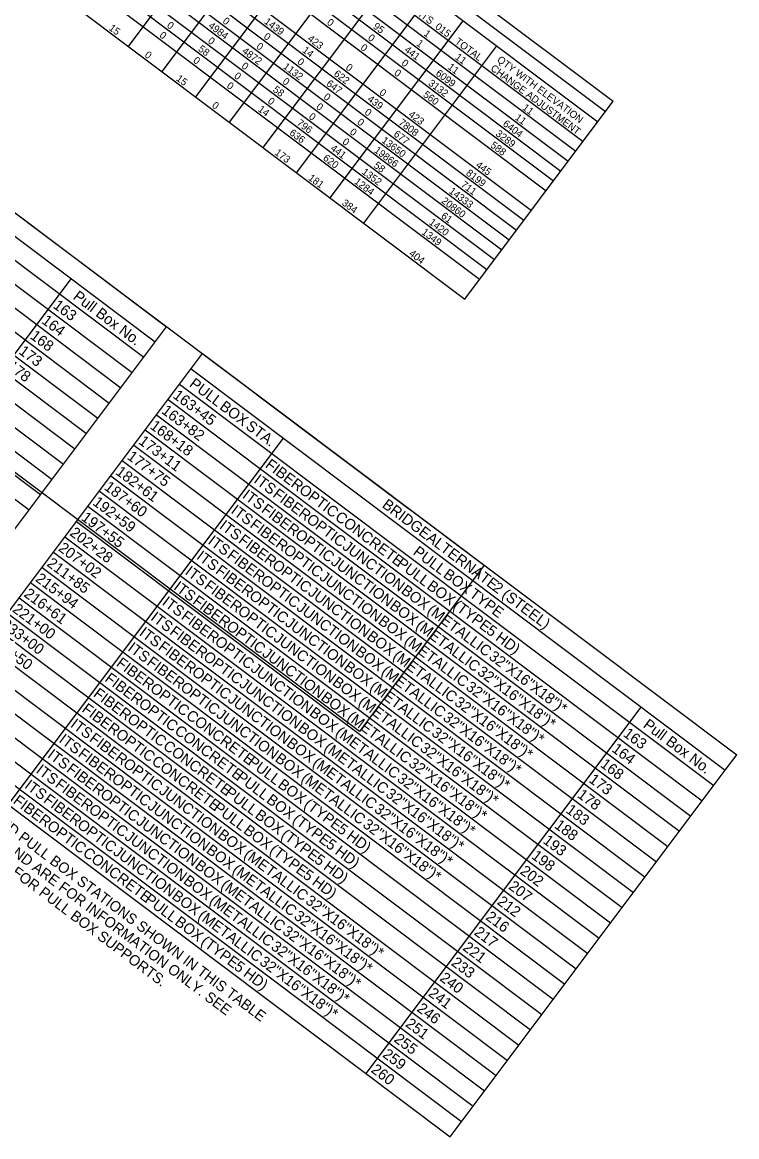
# Model space of a CAD drawing. Extents: x 626494 to 629419, y 365986 to 369334.
# Drawn here: x 628055 to 628332.4, y 367961.6 to 368394.1 of the extents above; entities that cross this region are included whole.
import ezdxf

# ---------------------------------------------------------------- set-up
doc = ezdxf.new("R2010")
doc.units = 0
for name, color, linetype in [('Default', 7, 'Continuous'), ('R_Grid_SCR50', 7, 'Continuous'), ('R_No Plot', 7, 'Continuous')]:
    doc.layers.add(name, color=color, linetype=linetype)

msp = doc.modelspace()

# ---------------------------------------------------------------- linework, layer by layer
at = {"layer": 'Default'}
for p, q in [((627992.22, 368582.9), (628284.46, 368363.46)), ((627989.23, 368578.92), (628281.47, 368359.47)), ((627980.5, 368567.29), (628272.74, 368347.85)), ((627977.63, 368563.47), (628269.87, 368344.03)), ((627974.76, 368559.65), (628267, 368340.2)), ((627971.89, 368555.83), (628264.13, 368336.38)), ((627969.02, 368552.01), (628261.26, 368332.56)), ((627966.15, 368548.18), (628258.39, 368328.74)), ((627957.54, 368536.72), (628249.78, 368317.27)), ((627960.41, 368540.54), (628252.65, 368321.09)), ((627954.67, 368532.89), (628246.91, 368313.45)), ((627951.8, 368529.07), (628244.04, 368309.63)), ((627948.93, 368525.25), (628241.17, 368305.8)), ((627946.05, 368521.43), (628238.3, 368301.98)), ((627943.18, 368517.61), (628235.43, 368298.16)), ((627940.31, 368513.78), (628232.56, 368294.34)), ((627934.57, 368506.14), (628226.82, 368286.69)), ((628095.65, 368492.78), (628278.48, 368355.49)), ((628096.22, 368384.76), (628147.89, 368453.56)), ((628109.28, 368374.95), (628160.94, 368443.75)), ((628122.34, 368365.14), (628174, 368433.94)), ((627911.88, 368425.51), (628111.03, 368275.96)), ((628135.4, 368355.34), (628187.06, 368424.14)), ((627907.43, 368419.58), (628106.58, 368270.04)), ((627902.97, 368413.65), (628102.13, 368264.11)), ((628148.46, 368345.53), (628200.12, 368414.33)), ((627898.52, 368407.73), (628097.68, 368258.18)), ((628161.52, 368335.72), (628213.18, 368404.52)), ((627894.07, 368401.8), (628093.22, 368252.26)), ((627889.62, 368395.87), (628088.77, 368246.33)), ((628174.58, 368325.92), (628226.24, 368394.72)), ((627885.17, 368389.95), (628084.32, 368240.4)), ((627880.72, 368384.02), (628079.87, 368234.47)), ((628187.64, 368316.11), (628239.3, 368384.91)), ((627876.27, 368378.09), (628075.42, 368228.55)), ((627871.82, 368372.16), (628070.97, 368222.62)), ((627867.37, 368366.24), (628066.52, 368216.69)), ((627862.92, 368360.31), (628062.07, 368210.77)), ((628226.82, 368286.69), (628284.46, 368363.46)), ((627858.47, 368354.38), (628057.62, 368204.84)), ((627967.16, 368152.27), (628073.98, 368294.52)), ((627999.76, 368127.79), (628111.03, 368275.96)), ((627999.76, 368127.79), (628111.03, 368275.96)), ((628013.69, 368117.33), (628124.96, 368265.5)), ((628013.69, 368117.33), (628124.96, 368265.5)), ((628124.96, 368265.5), (628332.41, 368109.73)), ((628120.51, 368259.58), (628327.95, 368103.8)), ((628116.05, 368253.65), (628323.5, 368097.88)), ((628111.6, 368247.72), (628319.05, 368091.95)), ((628107.15, 368241.8), (628314.6, 368086.02)), ((628102.7, 368235.87), (628310.15, 368080.09)), ((628049.55, 368090.4), (628156.36, 368232.65)), ((628098.25, 368229.94), (628305.7, 368074.17)), ((628093.8, 368224.02), (628301.25, 368068.24)), ((628089.35, 368218.09), (628296.8, 368062.31)), ((628084.9, 368212.16), (628292.35, 368056.39)), ((628080.45, 368206.23), (628287.9, 368050.46)), ((628076, 368200.31), (628283.45, 368044.53)), ((628071.55, 368194.38), (628279, 368038.6)), ((628067.1, 368188.45), (628274.55, 368032.68)), ((628062.65, 368182.53), (628270.1, 368026.75)), ((628058.2, 368176.6), (628265.64, 368020.82)), ((628053.74, 368170.67), (628261.19, 368014.9)), ((628049.29, 368164.74), (628256.74, 368008.97)), ((628044.84, 368158.82), (628252.29, 368003.04)), ((628040.39, 368152.89), (628247.84, 367997.11)), ((628035.94, 368146.96), (628243.39, 367991.19)), ((628031.49, 368141.04), (628238.94, 367985.26)), ((628027.04, 368135.11), (628234.49, 367979.33)), ((628022.59, 368129.18), (628230.04, 367973.41)), ((628188.54, 367986.03), (628295.36, 368128.28)), ((628188.54, 367986.03), (628295.36, 368128.28)), ((628018.14, 368123.25), (628225.59, 367967.48)), ((628013.69, 368117.33), (628221.14, 367961.55)), ((628327.95, 368103.8), (628332.41, 368109.73)), ((628221.14, 367961.55), (628327.95, 368103.8))]:
    msp.add_line(p, q, dxfattribs=at)
at = {"layer": 'R_No Plot'}
msp.add_line((628146.21, 368249.55), (628204.96, 368205.43), dxfattribs=at)
msp.add_lwpolyline([(627911.88, 368425.51), (628234.33, 368183.37), (628185.91, 368118.88), (627863.45, 368361.02)], close=True, dxfattribs=at)

# ---------------------------------------------------------------- texts
at = {"layer": 'Default'}
for s, height, p in [('ITS_015', 2.809, (628208.72, 368396.62)), ('0', 2.81, (628110.86, 368392.4)), ('0', 2.81, (628132.53, 368394.06)), ('1439', 2.809, (628148.67, 368393.89)), ('0', 2.81, (628173, 368393.55)), ('15', 2.809, (628088.34, 368391.38)), ('0', 2.81, (628107.99, 368388.57)), ('4984', 2.809, (628126.97, 368392.26)), ('0', 2.81, (628148.46, 368388.07)), ('95', 2.809, (628190.95, 368392.03)), ('1', 2.81, (628210.64, 368389.21)), ('58', 2.809, (628123.04, 368383.25)), ('0', 2.81, (628126.79, 368386.41)), ('0', 2.81, (628145.59, 368384.25)), ('423', 2.809, (628165.52, 368387.22)), ('0', 2.81, (628186.06, 368383.75)), ('0', 2.81, (628188.93, 368387.57)), ('1', 2.81, (628207.77, 368385.38)), ('TOTAL', 2.809, (628222.72, 368386.11)), ('0', 2.81, (628102.25, 368380.93)), ('4872', 2.809, (628140.07, 368382.42)), ('14', 2.809, (628163.49, 368382.77)), ('441', 2.809, (628203.1, 368382.91)), ('11', 2.809, (628222.8, 368380.07)), ('0', 2.81, (628121.05, 368378.77)), ('0', 2.81, (628139.85, 368376.61)), ('1132', 2.809, (628156, 368376.44)), ('0', 2.81, (628161.52, 368378.27)), ('0', 2.81, (628180.32, 368376.1)), ('0', 2.81, (628201.99, 368377.76)), ('11', 2.809, (628219.93, 368376.25)), ('CHANGE ADJUSTMENT', 2.8087, (628236.58, 368375.7)), ('QTY WITH ELEVATION', 2.8087, (628239.11, 368379.07)), ('15', 2.809, (628114.46, 368371.76)), ('0', 2.81, (628136.98, 368372.78)), ('0', 2.81, (628155.78, 368370.62)), ('622', 2.809, (628175.7, 368373.6)), ('0', 2.81, (628199.12, 368373.94)), ('6099', 2.809, (628215.26, 368373.78)), ('0', 2.81, (628134.11, 368368.96)), ('58', 2.809, (628152.03, 368367.46)), ('647', 2.809, (628172.81, 368369.79)), ('0', 2.81, (628193.38, 368366.3)), ('3132', 2.809, (628212.4, 368369.95)), ('0', 2.81, (628150.04, 368362.98)), ('0', 2.81, (628171.71, 368364.64)), ('439', 2.809, (628188.75, 368363.8)), ('560', 2.809, (628210.39, 368365.48)), ('0', 2.81, (628128.37, 368361.32)), ('14', 2.809, (628146.27, 368359.84)), ('0', 2.81, (628168.84, 368360.82)), ('0', 2.81, (628187.64, 368358.65)), ('11', 2.809, (628248.92, 368360.46)), ('796', 2.809, (628161.32, 368354.51)), ('0', 2.81, (628165.97, 368356.99)), ('0', 2.81, (628184.77, 368354.83)), ('7808', 2.809, (628200.89, 368354.68)), ('423', 2.809, (628204.7, 368357.8)), ('6404', 2.809, (628241.34, 368354.19)), ('11', 2.809, (628246.05, 368356.64)), ('636', 2.809, (628158.45, 368350.69)), ('0', 2.81, (628181.9, 368351.01)), ('677', 2.809, (628198.93, 368350.18)), ('3289', 2.809, (628238.51, 368350.34)), ('0', 2.81, (628179.03, 368347.19)), ('13650', 2.809, (628194.25, 368347.72)), ('588', 2.809, (628236.52, 368345.86)), ('173', 2.809, (628152.75, 368343.02)), ('620', 2.809, (628171.5, 368340.89)), ('441', 2.809, (628174.4, 368344.68)), ('19866', 2.809, (628191.38, 368343.89)), ('58', 2.809, (628191.21, 368338.04)), ('445', 2.809, (628230.81, 368338.19)), ('181', 2.809, (628165.79, 368333.22)), ('1284', 2.809, (628183.65, 368331.76)), ('1352', 2.809, (628186.57, 368335.55)), ('8199', 2.809, (628227.03, 368335.05)), ('14333', 2.809, (628220.41, 368328.07)), ('711', 2.809, (628225.06, 368330.55)), ('384', 2.809, (628178.81, 368323.45)), ('20860', 2.809, (628217.49, 368324.28)), ('1420', 2.809, (628212.65, 368315.96)), ('61', 2.809, (628217.35, 368318.41)), ('1349', 2.809, (628209.81, 368312.12)), ('404', 2.809, (628204.93, 368303.83)), ('163', 4.181, (628066.64, 368283.51)), ('Pull', 4.181, (628074.38, 368286.96)), (' Box', 4.181, (628081.9, 368281.32)), ('164', 4.181, (628062.19, 368277.58)), ('168', 4.181, (628057.74, 368271.65)), (' No.', 4.181, (628090.9, 368274.56)), ('173', 4.181, (628053.29, 368265.73)), ('178', 4.181, (628048.84, 368259.8)), ('PULL', 4.181, (628119.55, 368253.05)), ('163+45', 4.181, (628113.17, 368248.57)), (' BOX', 4.181, (628130.04, 368245.17)), ('163+82', 4.181, (628108.72, 368242.64)), ('168+18', 4.181, (628104.27, 368236.72)), (' STA.', 4.181, (628140.19, 368237.55)), ('173+11', 4.181, (628099.81, 368230.79)), ('177+75', 4.181, (628095.36, 368224.86)), ('182+61', 4.181, (628090.91, 368218.93)), ('FIBER', 4.181, (628149.03, 368221.64)), ('ITS', 4.181, (628144.58, 368215.72)), ('187+60', 4.181, (628086.46, 368213.01)), ('ITS', 4.181, (628140.12, 368209.79)), (' FIBER', 4.181, (628150.7, 368211.12)), (' OPTIC', 4.181, (628160.87, 368212.75)), ('192+59', 4.181, (628082.01, 368207.08)), ('BRIDGE', 4.181, (628194.39, 368206.12)), ('197+55', 4.181, (628077.56, 368201.15)), ('ITS', 4.181, (628135.67, 368203.86)), (' FIBER', 4.181, (628146.25, 368205.19)), (' CONCRETE', 4.181, (628174.84, 368202.26)), ('ITS', 4.181, (628131.22, 368197.93)), (' FIBER', 4.181, (628141.8, 368199.26)), (' OPTIC', 4.181, (628163.74, 368201.33)), ('202+28', 4.181, (628073.11, 368195.23)), ('ITS', 4.181, (628126.77, 368192.01)), (' FIBER', 4.181, (628137.35, 368193.34)), (' OPTIC', 4.181, (628159.29, 368195.4)), (' ALTERNATE', 4.181, (628210.3, 368194.17)), ('207+02', 4.181, (628068.66, 368189.3)), (' OPTIC', 4.181, (628154.84, 368189.47)), (' JUNCTION', 4.181, (628177.7, 368190.84)), ('PULL', 4.181, (628206.39, 368187.84)), ('ITS', 4.181, (628122.32, 368186.08)), (' FIBER', 4.181, (628132.9, 368187.41)), (' JUNCTION', 4.181, (628173.25, 368184.92)), (' PULL', 4.181, (628198.83, 368184.25)), ('211+85', 4.181, (628064.21, 368183.37)), ('ITS', 4.181, (628117.87, 368180.15)), (' FIBER', 4.181, (628128.45, 368181.48)), (' OPTIC', 4.181, (628150.39, 368183.55)), (' BOX', 4.181, (628216.87, 368179.96)), ('215+94', 4.181, (628059.76, 368177.44)), (' FIBER', 4.181, (628124, 368175.55)), (' OPTIC', 4.181, (628145.94, 368177.62)), (' JUNCTION', 4.181, (628168.8, 368178.99)), ('216+61', 4.181, (628055.31, 368171.52)), ('ITS', 4.181, (628113.42, 368174.23)), (' OPTIC', 4.181, (628141.48, 368171.69)), (' JUNCTION', 4.181, (628164.35, 368173.06)), (' BOX', 4.181, (628200.5, 368173.72)), (' BOX', 4.181, (628210.5, 368175.48)), (' TYPE', 4.181, (628227.03, 368172.34)), (' 2', 4.181, (628236.06, 368174.83)), (' (STEEL)', 4.181, (628239.63, 368172.15)), ('ITS', 4.181, (628108.97, 368168.3)), (' FIBER', 4.181, (628119.54, 368169.63)), (' BOX', 4.181, (628196.05, 368167.79)), (' (TYPE', 4.181, (628220.66, 368167.86)), ('221+00', 4.181, (628050.86, 368165.59)), ('ITS', 4.181, (628104.52, 368162.37)), (' FIBER', 4.181, (628115.09, 368163.7)), (' OPTIC', 4.181, (628137.03, 368165.76)), (' JUNCTION', 4.181, (628159.9, 368167.13)), (' (METALLIC', 4.181, (628210.65, 368166.1)), ('233+00', 4.181, (628046.41, 368159.66)), (' OPTIC', 4.181, (628132.58, 368159.84)), (' JUNCTION', 4.181, (628155.45, 368161.21)), (' BOX', 4.181, (628191.6, 368161.87)), (' (METALLIC', 4.181, (628206.2, 368160.17)), ('239+50', 4.181, (628041.95, 368153.74)), ('ITS', 4.181, (628100.07, 368156.44)), (' FIBER', 4.181, (628110.64, 368157.77)), (' JUNCTION', 4.181, (628150.99, 368155.28)), (' BOX', 4.181, (628187.15, 368155.94)), (' 5', 4.181, (628233.6, 368158.14)), (' HD)', 4.181, (628237.15, 368155.47)), ('ITS', 4.181, (628095.62, 368150.52)), (' FIBER', 4.181, (628106.19, 368151.85)), (' OPTIC', 4.181, (628128.13, 368153.91)), (' BOX', 4.181, (628182.7, 368150.01)), (' (METALLIC', 4.181, (628201.75, 368154.24)), ('FIBER', 4.181, (628091.17, 368144.59)), (' FIBER', 4.181, (628101.74, 368145.92)), (' OPTIC', 4.181, (628123.68, 368147.98)), (' JUNCTION', 4.181, (628146.54, 368149.35)), (' (METALLIC', 4.181, (628197.3, 368148.32)), (' 32"X16"X18")*', 4.1812, (628234.55, 368148.15)), (' OPTIC', 4.181, (628119.23, 368142.06)), (' JUNCTION', 4.181, (628142.09, 368143.43)), (' BOX', 4.181, (628178.25, 368144.09)), (' (METALLIC', 4.181, (628192.85, 368142.39)), (' 32"X16"X18")*', 4.1812, (628230.1, 368142.22)), ('FIBER', 4.181, (628086.72, 368138.66)), (' JUNCTION', 4.181, (628137.64, 368137.5)), (' BOX', 4.181, (628173.8, 368138.16)), ('FIBER', 4.181, (628082.26, 368132.74)), (' OPTIC', 4.181, (628103.01, 368135.69)), (' OPTIC', 4.181, (628114.78, 368136.13)), (' (METALLIC', 4.181, (628188.4, 368136.46)), (' 32"X16"X18")*', 4.1812, (628225.65, 368136.3)), (' OPTIC', 4.181, (628098.56, 368129.77)), (' JUNCTION', 4.181, (628133.19, 368131.57)), (' BOX', 4.181, (628169.35, 368132.23)), (' (METALLIC', 4.181, (628183.95, 368130.53)), (' 32"X16"X18")*', 4.1812, (628221.2, 368130.37)), ('FIBER', 4.181, (628077.81, 368126.81)), (' CONCRETE', 4.181, (628116.98, 368125.21)), (' JUNCTION', 4.181, (628128.74, 368125.64)), (' BOX', 4.181, (628164.9, 368126.3)), (' (METALLIC', 4.181, (628179.5, 368124.61)), (' 32"X16"X18")*', 4.1812, (628216.75, 368124.44)), ('ITS', 4.181, (628073.36, 368120.88)), (' OPTIC', 4.181, (628094.11, 368123.84)), (' BOX', 4.181, (628160.44, 368120.38)), ('Pull', 4.181, (628295.76, 368120.73)), ('ITS', 4.181, (628068.91, 368114.96)), (' FIBER', 4.181, (628079.49, 368116.28)), (' OPTIC', 4.181, (628089.66, 368117.91)), (' CONCRETE', 4.181, (628112.52, 368119.28)), (' (METALLIC', 4.181, (628175.05, 368118.68)), (' 32"X16"X18")*', 4.1812, (628212.3, 368118.51)), ('163', 4.181, (628288.02, 368117.27)), (' Box', 4.181, (628303.28, 368115.09)), (' CONCRETE', 4.181, (628108.07, 368113.36)), (' BOX', 4.181, (628155.99, 368114.45)), (' (METALLIC', 4.181, (628170.6, 368112.75)), (' 32"X16"X18")*', 4.1812, (628207.85, 368112.59)), ('164', 4.181, (628283.57, 368111.35)), ('ITS', 4.181, (628064.46, 368109.03)), (' FIBER', 4.181, (628075.04, 368110.36)), (' CONCRETE', 4.181, (628103.62, 368107.43)), (' PULL', 4.181, (628140.97, 368107.19)), (' BOX', 4.181, (628151.54, 368108.52)), (' (METALLIC', 4.181, (628166.15, 368106.83)), (' 32"X16"X18")*', 4.1812, (628203.4, 368106.66)), (' No.', 4.181, (628312.28, 368108.32)), ('ITS', 4.181, (628060.01, 368103.1)), (' FIBER', 4.181, (628070.59, 368104.43)), (' OPTIC', 4.181, (628092.53, 368106.49)), ('168', 4.181, (628279.12, 368105.42)), ('ITS', 4.181, (628055.56, 368097.17)), (' FIBER', 4.181, (628066.14, 368098.5)), (' OPTIC', 4.181, (628088.08, 368100.57)), (' PULL', 4.181, (628136.52, 368101.27)), (' BOX', 4.181, (628152.64, 368098.43)), (' (METALLIC', 4.181, (628161.7, 368100.9)), (' 32"X16"X18")*', 4.1812, (628198.95, 368100.73)), ('173', 4.181, (628274.66, 368099.49)), (' OPTIC', 4.181, (628083.63, 368094.64)), (' JUNCTION', 4.181, (628106.49, 368096.01)), (' PULL', 4.181, (628132.07, 368095.34)), (' 32"X16"X18")*', 4.1812, (628194.5, 368094.81)), ('178', 4.181, (628270.21, 368093.57)), ('FIBER', 4.181, (628051.11, 368091.25)), (' FIBER', 4.181, (628061.69, 368092.57)), (' JUNCTION', 4.181, (628102.04, 368090.08)), (' PULL', 4.181, (628127.62, 368089.41)), (' BOX', 4.181, (628148.19, 368092.5)), (' (TYPE', 4.181, (628162.8, 368090.8)), (' OPTIC', 4.181, (628079.17, 368088.71)), (' BOX', 4.181, (628143.74, 368086.57)), (' 32"X16"X18")*', 4.1812, (628190.05, 368088.88)), ('183', 4.181, (628265.76, 368087.64)), (' OPTIC', 4.181, (628062.96, 368082.35)), (' OPTIC', 4.181, (628074.72, 368082.78)), (' JUNCTION', 4.181, (628097.59, 368084.15)), (' BOX', 4.181, (628139.29, 368080.65)), (' (TYPE', 4.181, (628158.35, 368084.88)), (' 5', 4.181, (628175.74, 368081.09)), (' 32"X16"X18")*', 4.1812, (628185.6, 368082.95)), ('188', 4.181, (628261.31, 368081.71)), (' JUNCTION', 4.181, (628093.14, 368078.23)), (' BOX', 4.181, (628129.29, 368078.89)), (' (TYPE', 4.181, (628153.89, 368078.95)), (' HD)', 4.181, (628179.29, 368078.42)), ('193', 4.181, (628256.86, 368075.78)), (' JUNCTION', 4.181, (628088.68, 368072.3)), (' BOX', 4.181, (628124.84, 368072.96)), (' (TYPE', 4.181, (628149.44, 368073.02)), (' 5', 4.181, (628171.29, 368075.16)), (' HD)', 4.181, (628174.84, 368072.49)), (' CONCRETE', 4.181, (628076.92, 368071.87)), (' (METALLIC', 4.181, (628139.44, 368071.26)), (' 5', 4.181, (628166.84, 368069.23)), ('198', 4.181, (628252.41, 368069.86)), (' BOX', 4.181, (628120.39, 368067.03)), (' (METALLIC', 4.181, (628134.99, 368065.34)), (' 5', 4.181, (628162.38, 368063.3)), (' HD)', 4.181, (628170.39, 368066.57)), ('202', 4.181, (628247.96, 368063.93)), (' BOX', 4.181, (628115.94, 368061.11)), (' (METALLIC', 4.181, (628130.54, 368059.41)), (' HD)', 4.181, (628165.94, 368060.64)), (' BOX', 4.181, (628111.49, 368055.18)), ('207', 4.181, (628243.51, 368058)), (' PULL', 4.181, (628100.91, 368053.85)), (' (METALLIC', 4.181, (628126.09, 368053.48)), (' 32"X16"X18")*', 4.1812, (628163.34, 368053.32)), ('212', 4.181, (628239.06, 368052.08)), (' (METALLIC', 4.181, (628121.64, 368047.55)), (' 32"X16"X18")*', 4.1812, (628158.89, 368047.39)), ('216', 4.181, (628234.61, 368046.15)), (' BOX', 4.181, (628112.59, 368045.08)), (' 32"X16"X18")*', 4.1812, (628154.44, 368041.46)), ('217', 4.181, (628230.16, 368040.22)), (' (TYPE', 4.181, (628122.74, 368037.46)), (' 32"X16"X18")*', 4.1812, (628149.99, 368035.53)), ('221', 4.181, (628225.71, 368034.29)), (' 32"X16"X18")*', 4.1812, (628145.54, 368029.61)), ('233', 4.181, (628221.26, 368028.37)), (' 5', 4.181, (628135.68, 368027.74)), (' HD)', 4.181, (628139.23, 368025.08)), ('240', 4.181, (628216.81, 368022.44)), ('241', 4.181, (628212.35, 368016.51)), ('246', 4.181, (628207.9, 368010.59)), ('251', 4.181, (628203.45, 368004.66)), ('255', 4.181, (628199, 367998.73)), ('259', 4.181, (628194.55, 367992.8)), ('260', 4.181, (628190.1, 367986.88))]:
    msp.add_text(s, height=height, rotation=323.0968, dxfattribs=at).set_placement(p)
at = {"layer": 'R_Grid_SCR50'}
for s, p in [('* BRIDGE-MOUNTED PULL BOX STATIONS SHOWN IN THIS TABLE', (628008.52, 368110.45)), ('ARE APPROXIMATE AND ARE FOR INFORMATION ONLY. SEE', (628004.83, 368105.53)), ('BRIDGE PLAN SHEETS FOR PULL BOX SUPPORTS.', (628001.14, 368100.61))]:
    msp.add_text(s, height=4.1, rotation=323.0968, dxfattribs=at).set_placement(p)

doc.saveas('drawing.dxf')
